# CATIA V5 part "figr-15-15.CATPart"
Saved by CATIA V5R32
Part number: Part1
Bounding box of the stored display mesh (mm): x -75 to 75, y -66.397 to 33.603, z 0 to 1
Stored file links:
  D:\PROJECTS\Project 2022\CATIA V5 6R 2022\Resources\Part Files\c15_catia_v5_6r2022_prt\figr-15-15.CATPart
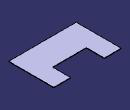
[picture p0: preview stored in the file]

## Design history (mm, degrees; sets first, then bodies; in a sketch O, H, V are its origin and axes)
SheetMetalParameters1: Thickness 1, BendRadius 1, KFactor 0.325257 {= log(min(100,max(20*SheetMetalParameters1.BendRadius,SheetMetalParameters1.Thickness)/SheetMetalParameters1.Thickness))/log(100)/2}, ReliefRadialLength 1, ReliefAxialLength 2, MinimumBendRadius 0
Body1 (main body)
  Sketch1 on xy-plane, origin (0, 0, 0), H (1, 0, 0), V (0, 1, 0)
    line L1 (-37.5, 33.6029) -> (-37.5, -6.3971)
    line L2 (-37.5, -6.3971) -> (37.5, -6.3971)
    line L3 (37.5, -6.3971) -> (37.5, 33.6029)
    line L4 (37.5, 33.6029) -> (75, 33.6029)
    line L5 (75, 33.6029) -> (75, -66.3971)
    line L6 (75, -66.3971) -> (-75, -66.3971)
    line L7 (-75, -66.3971) -> (-75, 33.6029)
    point P8 (-75, 33.6029)
    line L8 (-75, 33.6029) -> (-37.5, 33.6029)
    length L7 = 100
    length L1 = 40
    length L6 = 150
    distance L1 L3 = 75
    vertical: L1 V, L3 V, L5 V, L7 V
    horizontal: L2 H, L4 H, L6 H, L8 H
    coincidence: P8 L4
    symmetry: L7 L5 V, L1 L3 V
  Wall1: Thickness 1, Profile Sketch1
